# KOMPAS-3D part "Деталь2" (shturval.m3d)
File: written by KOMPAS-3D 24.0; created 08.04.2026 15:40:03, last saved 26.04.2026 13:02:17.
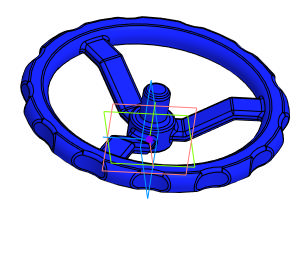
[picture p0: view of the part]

Document properties: Автор: R2D2; Полное имя файла: C:\Работа\VSO2130M-F-S Клапан запорный DN.ru\DN40\DN40\shturval.m3d

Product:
- Body: Твердое тело1  | qty 1
    Масса: 0.882711
- Part/product: Деталь2
    Масса: 0.882711
    additional columns: Типовые

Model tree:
1. Твердое тело1  (labels: Твердое тело1)
2. Масштабирование:1
3. Масштабирование : Твердое тело1
     Масштаб по оси Х = 1; Масштаб по оси Y = 1; Масштаб по оси Z = 1; Коэффициент = 1.084

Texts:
  Масштабирование : Вершина.Начало координат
